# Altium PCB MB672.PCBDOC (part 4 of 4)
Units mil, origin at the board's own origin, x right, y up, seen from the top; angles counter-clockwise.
Board outline 4505 x 6805 mil, 4 copper layers (TopLayer, GND, VCC, BottomLayer); 337 components, 289 nets, 1516 pads, 621 vias.
Unrouted connection lines stored in the file: 46.
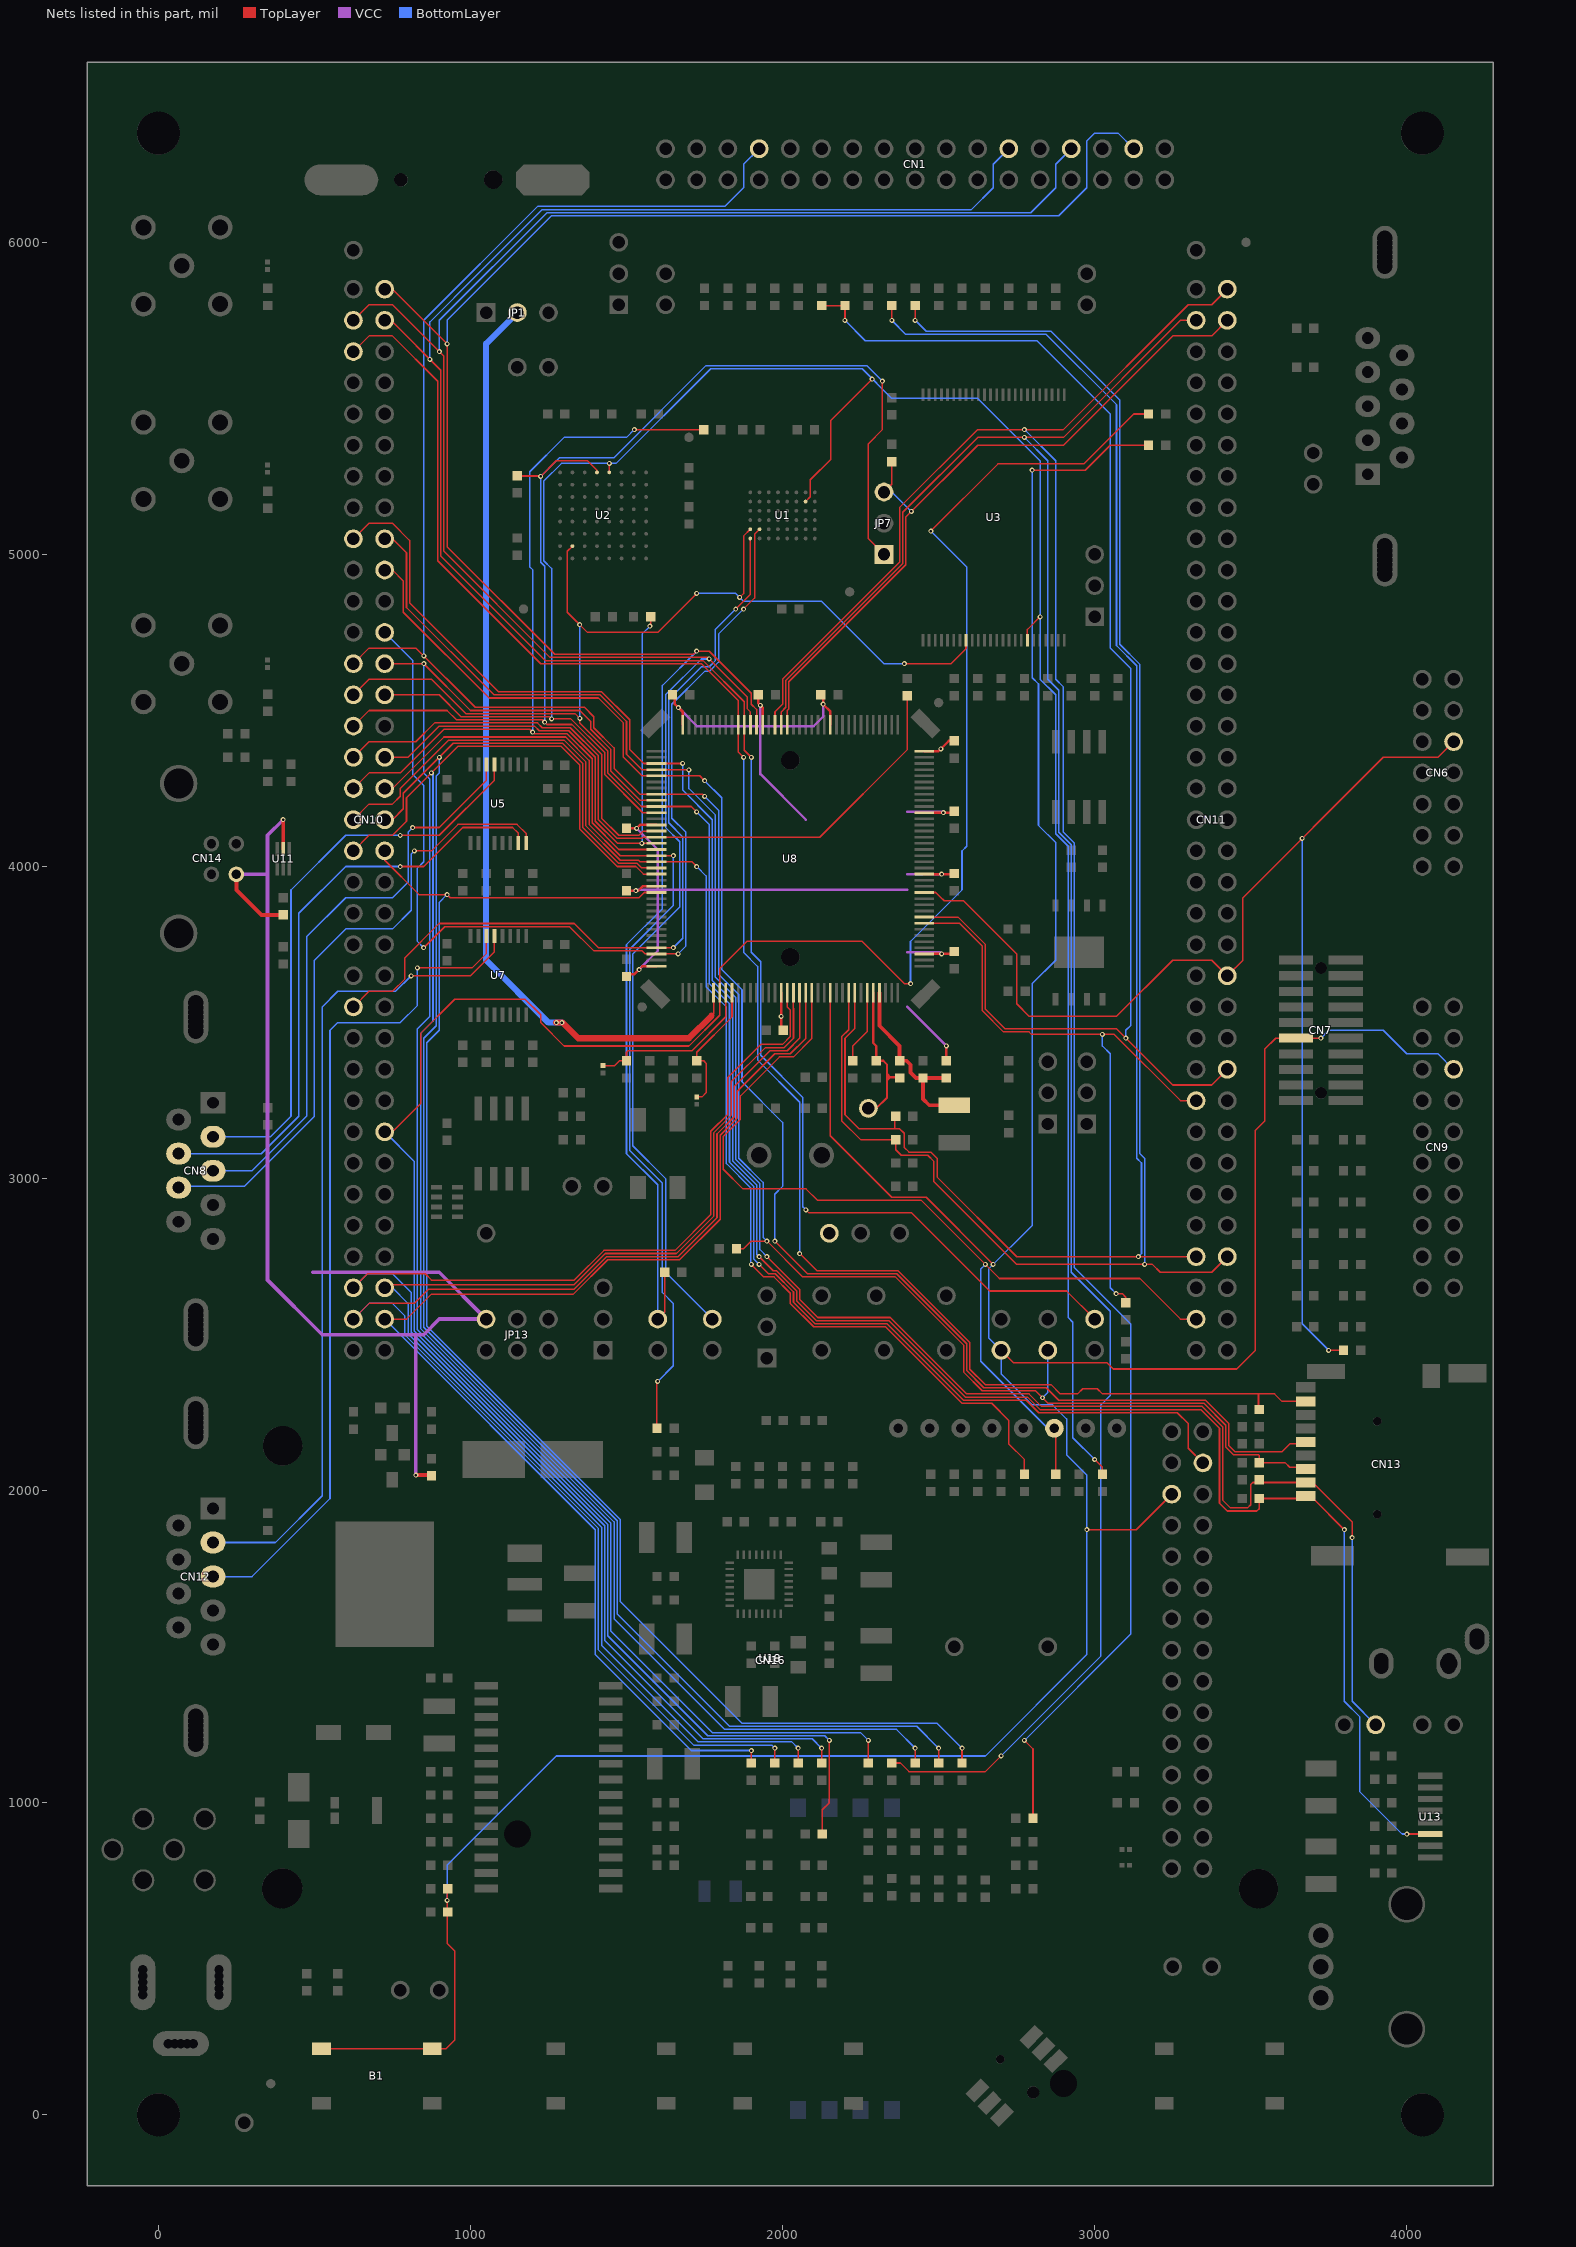
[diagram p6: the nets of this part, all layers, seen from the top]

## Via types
v1: diameter 16, hole 8, TopLayer to BottomLayer, tented both sides, 621 vias

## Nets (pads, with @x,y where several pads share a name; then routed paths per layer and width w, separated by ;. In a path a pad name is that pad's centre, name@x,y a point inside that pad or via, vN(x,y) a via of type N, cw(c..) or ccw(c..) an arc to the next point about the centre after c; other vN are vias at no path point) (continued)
PC2: C13.2 CN11.64 R4.1 U8.28 | length 5545
  TopLayer w5: U8.28@2212.01,3595.87 2212.01,3477.01 2190,3455 2190,3185 2250,3125 C13.2@2362.5,3125 2362.5,3092.5 2380,3075 2465,3075 2485,3055 2485,2990 2750,2725 3185,2725 3210,2700 3375,2700 CN11.64@3425,2750 ; v1(2425,5750) R4.1@2425,5797.5
  BottomLayer w5: v1(2425,5750) 2460,5715 2860,5715 3080,5495 3080,4712.43 3145,4647.43 3145,3080 3160,3065 v1(3160,2725)
PC3: C9.2 CN11.63 R3.1 U8.29 | length 5463.1
  TopLayer w5: U8.29@2231.69,3595.87 2231.69,3481.69 2200,3450 2200,3205 2245,3160 2375,3160 2390,3145 2390,3100 2405,3085 2475,3085 2495,3065 2495,3005 2750,2750 CN11.63@3325,2750 ; v1(2350,5750) R3.1@2350,5797.5 ; 2360,3160 C9.2@2360,3197.5
  BottomLayer w5: v1(2350,5750) 2395,5705 2845,5705 3070,5480 3070,4708.28 3135,4643.28 3135,3065 3150,3050 3150,2760 v1(3140,2750)
PC4: CN11.53 R126.1 U8.44 | length 2132.1
  TopLayer w5: U8.44@2454.13,3818.31 2566.69,3818.31 2640,3745 2640,3538.28 2708.28,3470 2790,3470 2798,3462 3063,3462 3275,3250 CN11.53@3325,3250 ; v1(3068.5,2631.5) 3088.5,2631.5 3100,2620 R126.1@3100,2602.5 R126.1@3097.5,2602.5
  BottomLayer w5: v1(3025,3462) 3025,3425 3050,3400 3050,2650 v1(3068.5,2631.5)
PC5: C6.2 CN11.52 R1.2 U8.45 | length 4465.9
  TopLayer w5: R1.2@2125,5797.5 C6.2@2200,5797.5 v1(2200,5750) ; U8.45@2454.13,3837.99 2562.01,3837.99 2650,3750 2650,3542.43 2712.43,3480 3070,3480 3250,3300 3375,3300 CN11.52@3425,3350
  BottomLayer w5: v1(2200,5750) 2265,5685 2815,5685 3050,5450 3050,4700 3115,4635 3115,3490 3100,3475 v1(3100,3450)
PC6: CN1.3 CN10.2 JP15.1 R56.2 U8.96 | length 7269.3
  TopLayer w5: CN10.2@725,5850 750,5850 v1(925,5675) 925,5025 1270,4680 1715,4680 v1(1725,4690) 1765,4690 1900,4555 1900,4520 1916.73,4503.27 U8.96@1916.73,4454.13 ; JP15.1@1600,2550 1622.5,2572.5 R56.2@1622.5,2700
  BottomLayer w5: v1(925,5675) 925,5750 1260,6085 2885,6085 2975,6175 2975,6325 3000,6350 3075,6350 CN1.3@3125,6300 ; JP15.1@1600,2555 1600,2980 1500,3080 1500,3750 1615,3865 1615,4580 v1(1725,4690)
PC7: CN1.7 CN10.3 JP16.1 U8.97 | length 7033.7
  TopLayer w5: CN10.3@625,5750 675,5800 750,5800 915,5635 915,5010 1255,4670 1760,4670 1887.36,4542.64 1887.36,4505 1897.05,4495.32 U8.97@1897.05,4454.13
  BottomLayer w5: v1(900,5650) 900,5750 1245,6095 2795,6095 2875,6175 2875,6250 CN1.7@2925,6300 ; v1(1765,4665) 1740,4665 1625,4550 1625,4125 1670.44,4079.56 1670.44,3870.44 1520,3720 1520,3105 1625,3000 1625,2700 JP16.1@1775,2550
PC8: CN1.11 CN10.4 JP17.1 U8.98 | length 7035.5
  TopLayer w5: CN10.4@725,5750 745,5750 905,5590 905,4995 1240,4660 1745,4660 1877.36,4527.64 1877.36,4372.64 v1(1900,4350) ; v1(2075,2900) 2085,2890 2414.14,2890 2664.14,2640 2910,2640 JP17.1@3000,2550
  BottomLayer w5: v1(870,5625) 870,5745 1025,5900 1056.28,5931.28 1230,6105 2605,6105 2675,6175 2675,6250 CN1.11@2725,6300 ; v1(1900,4350) 1900,3725 1930,3695 1930,3395 2065,3260 2065,2910 v1(2075,2900)
PC9: CN10.5 CN13.8 R131.2 U8.99 | length 5857.6
  TopLayer w5: CN10.5@625,5650 675,5700 750,5700 895,5555 895,4980 1225,4650 1740,4650 1857.68,4532.32 1857.68,4367.32 v1(1875,4350) ; v1(2055,2760) 2110,2705 2370,2705 2600,2475 2600,2389.14 2649.14,2340 2860,2340 2890,2310 2945,2310 2961.84,2326.84 3008.16,2326.84 3025,2310 3576.22,2310 3600,2286.22 CN13.8@3676.65,2286.22 ; R131.2@3525,2262.5 3525,2310
  BottomLayer w5: v1(1875,4350) 1875,3725 1920,3680 1920,3380 2055,3245 v1(2055,2760)
PC10: CN10.17 CN13.1 R132.2 U8.111 U13.3 | length 6840
  TopLayer w5: CN10.17@625,5050 675,5100 750,5100 805,5045 805,4845 1090,4560 1420,4560 1510,4470 1510,4375.12 1555,4330.12 v1(1680.12,4330.12) ; v1(1925,2750) 1970,2705 1980.86,2705 2045,2640.86 2045,2608.28 2108.28,2545 2340,2545 2585,2300 2785,2300 2825,2260 3340,2260 3400,2200 3400,1960 3425,1935 3520,1935 3527.5,1942.5 R132.2@3527.5,1975 3700,1975 v1(3800,1875) ; v1(4000,900) 4074.8,900 U13.3@4075,899.8
  BottomLayer w5: v1(1680.12,4330.12) 1680.12,4244.88 1775,4150 1775,3635 1840,3570 1840,3056.72 1917.5,2979.22 1917.5,2757.5 v1(1925,2750) ; v1(3800,1875) 3800,1325 3850,1275 3850,1035 3985,900 v1(4000,900)
PC11: CN10.18 CN13.2 JP22.1 R133.2 U8.112 | length 6279.5
  TopLayer w5: CN10.18@725,5050 750,5050 795,5005 795,4830 1075,4550 1415,4550 1500,4465 1500,4360 1549.57,4310.43 1699.57,4310.43 v1(1700,4310) ; v1(1950,2750) 2055,2645 2055,2612.43 2112.43,2555 2345,2555 2590,2310 2790,2310 2830,2270 3345,2270 3410,2205 3410,1970 3435,1945 3490,1945 3500,1955 3500,2020 3506.38,2026.38 3698.62,2026.38 3825,1900 v1(3825,1850)
  BottomLayer w5: v1(1700,4310) 1700,4250 1785,4165 1785,3645 1850,3580 1850,3060.86 1927.5,2983.36 1927.5,2772.5 v1(1950,2750) ; v1(3825,1850) 3825,1325 JP22.1@3900,1250
PC12: CN10.20 CN13.5 U8.113 | length 5102.8
  TopLayer w5: CN10.20@725,4950 750,4950 785,4915 785,4815 1060,4540 1410,4540 1490,4460 1490,4350 1549.25,4290.75 1734.25,4290.75 v1(1750,4275) ; v1(1975,2800) 2080,2695 2365.86,2695 2590,2470.86 2590,2385 2645,2330 2845,2330 2885,2290 3355,2290 3430,2215 3430,2145 3450,2125 3600,2125 3625,2150 CN13.5@3680,2150
  BottomLayer w5: v1(1750,4275) 1805,4220 1805,3670 1870,3605 1870,3310 2000,3180 2000,2975 1975,2950 v1(1975,2800)
PC13: CN10.56 R11.1 R111.2 U8.7 | length 7846.4
  TopLayer w5: CN10.56@725,3150 750,3150 840,3240 840,3465 950,3575 1175,3575 1225,3525 1225,3500 1300,3425 1700,3425 1798.62,3523.62 1798.62,3673.62 1885,3760 2255,3760 2390,3625 v1(2410,3625) ; R111.2@2127.5,900 2127.5,977.5 2150,1000 v1(2150,1200) ; v1(2475,5075) 2690,5290 2965,5290 3125,5450 R11.1@3172.5,5450
  BottomLayer w5: CN10.56@725,3150 820,3055 820,2511.57 1440,1891.57 1440,1535 1760,1215 2135,1215 v1(2150,1200) ; v1(2410,3625) 2410,3760 2575,3925 2575,4050 2590,4065 2590,4960 v1(2475,5075)
PC14: JP9.1 R135.2 U8.8 | length 551.8
  TopLayer w5: JP9.1@1425,3361.81 1461.81,3361.81 1477.5,3377.5 R135.2@1500,3377.5 1500,3405 1505,3410 1710,3410 1818.31,3518.31 U8.8@1818.31,3595.87
PC15: JP10.2 R39.2 U8.9 | length 428.7
  TopLayer w5: JP10.2@1725,3261.81 1741.81,3261.81 1755,3275 1755,3370 1747.5,3377.5 R39.2@1725,3377.5 1725,3405 1837.99,3517.99 U8.9@1837.99,3595.87
PD2: C60.2 CN1.27 CN10.25 CN13.3 JP20.1 R134.2 U8.116 | length 7723.2
  TopLayer w5: CN10.25@625,4650 675,4700 825,4700 1015,4510 1365,4510 1395,4480 1395,4445 1460,4380 1460,4315 1543.31,4231.69 1743.31,4231.69 v1(1750,4225) ; C60.2@1852.5,2775 1875,2775 1900,2800 v1(1950,2800) 2065,2685 2361.72,2685 2580,2466.72 2580,2380 2640,2320 2810.74,2320 2850.74,2280 3350,2280 3420,2210 3420,2140 3445,2115 3525,2115 3527.5,2112.5 R134.2@3527.5,2090 3610,2090 3625,2075 CN13.3@3670,2075
  BottomLayer w5: v1(850.35,4674.65) 850.35,5750.35 1215,6115 1815,6115 1875,6175 1875,6250 CN1.27@1925,6300 ; v1(1750,4225) 1795,4180 1795,3655 1860,3590 1860,3065 1937.5,2987.5 1937.5,2812.5 v1(1950,2800) ; v1(2832.87,2297.87) 2850,2315 JP20.1@2850,2450
PD3: CN10.26 R100.2 U8.117 | length 5532.8
  TopLayer w5: CN10.26@725,4650 v1@850,4650 ; v1(850.35,4650.35) v1@850,4650 ; U8.117@1595.87,4212.01 1542.99,4212.01 1450,4305 1450,4375 1385,4440 1385,4465 1350,4500 1000,4500 v1@850,4650 ; R100.2@2275,1127.5 v1(2275,1200)
  BottomLayer w5: v1(850.35,4650.35) 850.35,4299.65 870,4280 870,3520 830,3480 830,2515.71 1450,1895.71 1450,1550 1775,1225 2250,1225 v1(2275,1200)
PD4: CN10.27 CN16.4 U1.A2 U2.G2 U3.8 U8.118 | length 6877.7
  TopLayer w5: CN10.27@625,4550 675,4600 875,4600 985,4490 1335,4490 v1(1350.36,4474.64) 1350.36,4459.64 1440,4370 1440,4300 1547.68,4192.32 1707.68,4192.32 v1(1725,4175) ; U2.G2@1326.57,5026.57 1310,5010 1310,4815 1375,4750 1600,4750 v1(1725,4875) ; v1(1862.61,4862.39) 1875,4874.78 1875,5059.06 U1.A2@1896.65,5080.71 ; v1(1925,2725) 1955,2695 1976.72,2695 2035,2636.72 2035,2604.14 2104.14,2535 2335,2535 2580,2290 2780.86,2290 2820.86,2250 3265,2250 3300,2215 3300,2136 CN16.4@3347,2089 ; v1(2390,4650) 2540,4650 2587.8,4697.8 U3.8@2587.8,4725
  BottomLayer w5: v1@1350,4475 v1(1350,4775) ; v1(1725,4175) 1765,4135 1765,3625 1830,3560 1830,3052.57 1907.5,2975.07 1907.5,2742.5 v1(1925,2725) ; v1(1725,4875) 1850,4875 1875,4850 2125,4850 2325,4650 v1(2390,4650)
PD5: CN10.28 R80.1 U1.G5 U2.A5 U3.18 U8.119 | length 7633.3
  TopLayer w5: CN10.28@725,4550 900,4550 970,4480 1253,4480 v1(1260,4473) 1322,4473 1430,4365 1430,4295 1552.36,4172.64 U8.119@1595.87,4172.64 ; U2.A5@1444.68,5262.8 v1@1444.68,5291.21 ; U1.G5@2073.82,5169.29 2089,5184.47 2089,5239 2155,5305 2155,5430 v1(2286.99,5561.99) ; U3.18@2784.65,4725 2784.65,4759.65 v1(2825,4800) ; v1(3000,2100) 3025,2075 R80.1@3025,2052.5
  BottomLayer w5: v1(1260,4473) 1260,4955 1235,4980 1235,5235 1291.52,5291.52 1466.52,5291.52 1770,5595 2255,5595 2350,5500 2625,5500 2825,5300 2825,4600 2875,4550 2875,4105 2915,4065 2915,2555 2930,2540 2930,2170 v1(3000,2100)
  other v1: 1445,5291.52
PD6: CN10.29 JP7.1 R18.1 U2.A4 U8.122 | length 4225.9
  TopLayer w5: CN10.29@625,4450 675,4500 925,4500 955,4470 1230,4470 1245,4455 1325,4455 1420,4360 1420,4155 1475,4100 1540,4100 1553.58,4113.58 U8.122@1595.87,4113.58 ; R18.1@1151.14,5251.36 v1@1223.64,5251.36 ; v1(1225,5250) 1275,5300 1375,5300 1405.31,5269.69 U2.A4@1405.31,5262.8 ; v1(2320,5555) 2320,5400 2275,5355 2275,5050 JP7.1@2325,5000
  BottomLayer w5: v1(1237.61,4462.39) 1237.61,4962.39 1225,4975 v1(1225,5250) 1285,5310 1460,5310 1755,5605 2270,5605 v1(2320,5555)
PD7: CN10.31 R22.1 U8.123 | length 2384.5
  TopLayer w5: CN10.31@625,4350 675,4400 825,4400 885,4460 1215,4460 1230,4445 1320,4445 1410,4355 1410,4150 1470,4090 1550,4090 1553.9,4093.9 2118.9,4093.9 2400,4375 R22.1@2400,4547.5
PE0: CN10.47 U1.A1 U8.141 | length 2673.6
  TopLayer w5: CN10.47@625,3550 675,3600 750,3600 790,3640 790,3708 899.36,3817.36 1332.64,3817.36 1410.43,3739.57 U8.141@1595.87,3739.57 1596.3,3740 v1(1650,3740) ; v1(1850,4825) 1896.65,4871.65 U1.A1@1896.65,5051.18
  BottomLayer w5: v1(1650,3740) 1680.44,3770.44 1680.44,4094.56 1635,4140 1635,4535 1740,4640 1765,4640 1785,4660 1785,4760 v1(1850,4825)
PE1: CN10.24 U1.B2 U8.142 | length 3472.9
  TopLayer w5: v1(850,3740) 917.36,3807.36 1317.64,3807.36 1395.43,3729.57 1550.43,3729.57 1560.12,3719.88 v1(1665,3719.88) ; v1(1875,4825) 1910.47,4860.47 1910.47,5065 U1.B2@1926.18,5080.71
  BottomLayer w5: CN10.24@725,4750 815,4660 815,4295 850,4260 850,4015 830,3995 830,3760 v1(850,3740) ; v1(1665,3719.88) 1690.44,3745.33 1690.44,4109.56 1645,4155 1645,4520 1750,4625 1765,4625 1795,4655 1795,4745 v1(1875,4825)
PF6: CN10.65 R96.2 U8.18 | length 4606.2
  TopLayer w5: CN10.65@625,2650 670,2695 855,2695 875,2675 1332.57,2675 1427.57,2770 1655,2770 1770,2885 1770,3151.57 1825,3206.57 1825,3325 1930,3430 2000,3430 2025,3455 2025,3540 2015.16,3549.84 U8.18@2015.16,3595.87 ; R96.2@2125,1127.5 v1(2125,1175)
  BottomLayer w5: CN10.65@625,2650 670,2695 750,2695 810,2635 810,2507.43 1430,1887.43 1430,1520 1745,1205 2095,1205 v1(2125,1175)
PF7: CN10.66 R97.2 U8.19 | length 4268.7
  TopLayer w5: CN10.66@725,2650 735,2660 1331.72,2660 1431.72,2760 1660,2760 1780,2880 1780,3147.43 1835,3202.43 1835,3310 1945,3420 2005,3420 2035,3450 2035,3545 2034.84,3545.16 U8.19@2034.84,3595.87 ; R97.2@2050,1127.5 v1(2050,1175)
  BottomLayer w5: CN10.66@725,2650 750,2650 800,2600 800,2503.28 1420,1883.28 1420,1505 1730,1195 2030,1195 v1(2050,1175)
PF8: CN10.67 R98.2 U8.20 | length 4434.3
  TopLayer w5: CN10.67@625,2550 675,2600 820,2600 865,2645 1330.86,2645 1435.86,2750 1665,2750 1790,2875 1790,3143.28 1845,3198.28 1845,3295 1960,3410 2015,3410 2054.53,3449.53 U8.20@2054.53,3595.87 ; R98.2@1975,1127.5 v1(1975,1175)
  BottomLayer w5: CN10.67@625,2550 675,2600 750,2600 790,2560 790,2499.14 1410,1879.14 1410,1490 1715,1185 1965,1185 v1(1975,1175)
PF9: CN10.68 R99.2 U8.21 | length 4098.3
  TopLayer w5: CN10.68@725,2550 795,2550 875,2630 1330,2630 1440,2740 1670,2740 1800,2870 1800,3139.14 1855,3194.14 1855,3280 1975,3400 2025,3400 2074.21,3449.21 U8.21@2074.21,3595.87 ; R99.2@1900,1127.5 v1(1900,1167.52)
  BottomLayer w5: CN10.68@725,2550 1400,1875 1400,1475 1707.48,1167.52 v1(1900,1167.52)
PF10: CN11.67 R78.1 U8.22 U18.6 | length 3208.5
  TopLayer w5: U8.22@2093.9,3595.87 2093.9,3448.9 2035,3390 1990,3390 1865,3265 1865,3190 1810,3135 1810,3030 1872.93,2967.07 2075.36,2967.07 2112.43,2930 2445,2930 2695,2680 3145,2680 3275,2550 CN11.67@3325,2550 ; R78.1@2875,2052.5 U18.6@2875,2196.06
  BottomLayer w5: v1(2650,2725) 2635,2710 2635,2415 2850,2200 U18.6@2871.06,2200
PF11: CN6.9 CN11.46 R129.1 U8.49 | length 4198.7
  TopLayer w5: U8.49@2454.13,3916.73 2490.94,3916.73 2502.65,3905.03 ; 2503.36,3904.32 2517.68,3890 2580,3890 2750,3720 2750,3560 2790,3520 3070,3520 3250,3700 3375,3700 CN11.46@3425,3650 3475,3700 3475,3900 3925,4350 4100,4350 CN6.9@4150,4400 ; v1(3750,2450) R129.1@3797.5,2450
  BottomLayer w5: v1(3665,4090) 3665,2535 v1(3750,2450)
PG6: CN11.4 JP7.3 R17.1 U8.91 | length 2335.5
  TopLayer w5: U8.91@2015.16,4454.13 2015.16,4500.16 2020,4505 2020,4591.72 2395,4966.72 2395,5120 2625,5350 2900,5350 3250,5700 3375,5700 CN11.4@3425,5750 ; JP7.3@2325,5200 2350,5225 R17.1@2350,5297.5
  BottomLayer w5: JP7.3@2325,5200 2350,5200 2412.38,5137.62 v1(2412.62,5137.62)
PG7: CN11.3 R101.2 U8.92 | length 6902.9
  TopLayer w5: U8.92@1995.47,4454.13 1995.47,4495.47 2010,4510 2010,4595.86 2385,4970.86 2385,5135 2625,5375 2900,5375 3275,5750 CN11.3@3325,5750 ; R101.2@2350,1127.5 2377.5,1127.5 2405,1100 2650,1100 v1(2700,1150)
  BottomLayer w5: v1(2700,1150) 3020,1470 3020,2275 3050,2305 3050,2575 2925,2700 2925,4070 2885,4110 2885,4565 2850,4600 2850,5300 v1(2775,5375)
PG8: CN11.2 R106.2 U8.93 | length 6944.2
  TopLayer w5: U8.93@1975.79,4454.13 1975.79,4495.79 2000,4520 2000,4600 2375,4975 2375,5150 2625,5400 2900,5400 3300,5800 3375,5800 CN11.2@3425,5850 ; v1(2775,1200) 2802.5,1172.5 R106.2@2802.5,950
  BottomLayer w5: v1(2775,1200) 3115,1540 3115,2535 2935,2715 2935,4075 2900,4110 2900,4575 2875,4600 2875,5300 v1(2775,5400)
PG9: CN10.32 R21.1 U8.124 | length 1923.5
  TopLayer w5: CN10.32@725,4350 800,4350 900,4450 1205,4450 1220,4435 1315,4435 1400,4350 1400,4145 1470.79,4074.21 v1@1548,4074.21 ; v1@1548.88,4074.21 U8.124@1595.87,4074.21 ; v1(1575,4770) 1577.5,4772.5 R21.1@1577.5,4800
  BottomLayer w5: v1@1550,4075 1550,4745 v1(1575,4770)
  other v1: 1548.88,4073.88
PG10: CN10.33 R15.1 U8.125 | length 2781.3
  TopLayer w5: CN10.33@625,4250 675,4300 775,4300 915,4440 1190,4440 1205,4425 1310,4425 1390,4345 1390,4140 1475.47,4054.53 U8.125@1595.87,4054.53 ; v1(1525,5400) R15.1@1747.5,5400
  BottomLayer w5: v1(1199.04,4430.96) 1200,4431.92 1200,4950 1190,4960 1190,5265 1300,5375 1500,5375 v1(1525,5400)
PG11: CN10.34 R128.2 U8.126 | length 3243.7
  TopLayer w5: CN10.34@725,4250 750,4250 915,4415 1305,4415 1380,4340 1380,4135 1480.16,4034.84 U8.126@1595.87,4034.84 1596.02,4035 v1(1650,4035) ; R128.2@1597.5,2200 1597.5,2347.5 v1(1600,2350)
  BottomLayer w5: v1(1600,2350) 1650,2400 1650,2600 1615,2635 1615,2985 1510,3090 1510,3735 1650,3875 v1(1650,4035)
PG12: CN10.35 R77.1 U8.127 | length 4100
  TopLayer w5: CN10.35@625,4150 675,4200 750,4200 775,4225 775,4250 930,4405 1300,4405 1370,4335 1370,4130 1480,4020 1538.28,4020 1543.13,4015.16 1709.84,4015.16 v1(1725,4000) ; v1(1900,2725) 1940,2685 1972.57,2685 2025,2632.57 2025,2600 2100,2525 2330,2525 2575,2280 2670,2280 2725,2225 2725,2150 2775,2100 R77.1@2775,2052.5
  BottomLayer w5: v1(1725,4000) 1755,3970 1755,3615 1820,3550 1820,3048.43 1897.5,2970.93 1897.5,2727.5 v1(1900,2725)
PG13: CN10.36 R103.2 U8.128 | length 5565.3
  TopLayer w5: CN10.36@725,4150 750,4150 785,4185 785,4235 945,4395 1295,4395 1360,4330 1360,4125 1475,4010 1534.14,4010 1548.67,3995.47 U8.128@1595.87,3995.47 ; R103.2@2500,1127.5 v1(2500,1175)
  BottomLayer w5: v1(900,4350) 900,4300 890,4290 890,3490 850,3450 850,2524 1470,1904 1470,1605 1830,1245 2430,1245 v1(2500,1175)
PG14: CN10.37 R102.2 U8.129 | length 5613
  TopLayer w5: CN10.37@625,4050 675,4100 750,4100 795,4145 795,4220 960,4385 1290,4385 1350,4325 1350,4120 1470,4000 1530,4000 1554.21,3975.79 U8.129@1595.87,3975.79 ; R102.2@2425,1127.5 v1(2425,1175)
  BottomLayer w5: v1(875,4300) 880,4295 880,3505 840,3465 840,2519.85 1460,1899.85 1460,1590 1815,1235 2365,1235 v1(2425,1175)
PG15: CN10.38 R104.2 U8.132 | length 4843.4
  TopLayer w5: CN10.38@725,4050 725,4020 835,3910 v1(925,3910) 935,3900 1540,3900 1556.73,3916.73 U8.132@1595.87,3916.73 ; R104.2@2575,1127.5 v1(2575,1175)
  BottomLayer w5: v1(925,3910) 900,3885 900,3475 860,3435 860,2528.14 1480,1908.14 1480,1645 1870,1255 2495,1255 v1(2575,1175)
RESET#: B1.2 B1.3 C94.2 CN7.10 CN9.15 CN16.5 JP19.2 R14.2 R119.1 U8.25 | length 11857.3
  TopLayer w5: B1.2@522.83,212.5 922.5,212.5 950,240 950,525 925,550 R119.1@925,722.5 ; U8.25@2152.95,3595.87 2152.95,3137.05 2350,2940 2460,2940 v1(2675,2725) ; JP19.2@2700,2450 2740,2410 3039.85,2410 3059.85,2390 3455,2390 3515,2450 3515,3155 3545,3185 3545,3415 3580,3450 v1(3725,3450) ; v1(2800,5270) 2970,5270 3050,5350 R14.2@3172.5,5350 ; v1(2975,1875) 3133,1875 CN16.5@3247,1989
  BottomLayer w5: v1(925,687.5) 925,800 1275,1150 2650,1150 2975,1475 2975,2050 2910,2115 2910,2230 2865,2275 2800,2275 2700,2375 JP19.2@2700,2450 2660,2490 2660,2710 2800,2850 2800,3625 2875,3700 2875,4076.72 2820,4131.72 2820,4585 2800,4605 v1(2800,5270) ; v1(3725,3450) 3750,3475 3925,3475 4000,3400 4100,3400 CN9.15@4150,3350
RS232_CTS2: CN8.8 U5.8 | length 2031.4
  TopLayer w5: v1(820,4050) 875,4050 960,4135 1149.13,4135 1179.13,4105 U5.8@1179.13,4075
  BottomLayer w5: CN8.8@69,2975 275,2975 500,3200 500,3700 600,3800 750,3800 810,3860 810,4040 v1(820,4050)
RS232_RTS2: CN8.7 U5.7 | length 1941.3
  TopLayer w5: v1(775,4000) 850,4000 975,4125 1135,4125 1153.54,4106.46 U5.7@1153.54,4075
  BottomLayer w5: CN8.7@65,3080 330,3080 450,3200 450,3850 600,4000 v1(775,4000)
RS232_RX1: CN12.2 U7.13 | length 2653.3
  TopLayer w5: v1(810,3650) 1000,3650 1076.77,3726.77 U7.13@1076.77,3776.97
  BottomLayer w5: CN12.2@175,1834 375,1834 525,1984 525,3550 575,3600 760,3600 v1(810,3650)
RS232_RX2: CN8.2 U5.13 | length 1850
  TopLayer w5: v1(775,4100) 900,4100 1076.77,4276.77 U5.13@1076.77,4326.97
  BottomLayer w5: CN8.2@175,3134 359,3134 425,3200 425,3925 600,4100 v1(775,4100)
RS232_TX1: CN12.3 U7.14 | length 2707.8
  TopLayer w5: v1(830,3675) 1005,3675 1051.18,3721.18 U7.14@1051.18,3776.97
  BottomLayer w5: CN12.3@175,1725 300,1725 550,1975 550,3475 575,3500 775,3500 830,3555 v1(830,3675)
RS232_TX2: CN8.3 U5.14 | length 1875.8
  TopLayer w5: v1(815,4125) 900,4125 1051.18,4276.18 U5.14@1051.18,4326.97
  BottomLayer w5: CN8.3@175,3025 300,3025 475,3200 475,3775 600,3900 750,3900 800,3950 800,4110 v1(815,4125)
U5V: C74.2 CN14.1 JP13.2 R70.1 U11.5 | length 3830.4
  TopLayer w12: CN14.1@250,3975 250,3925 330,3845 C74.2@400,3845 ; U11.5@400,4056.3 v1(400,4150) ; v1(825,2050) R70.1@872.5,2050
  VCC w12: CN14.1@250,3975 350,3975 ; v1(400,4150) 350,4100 350,2675 525,2500 850,2500 900,2550 JP13.2@1050,2550 900,2700 495,2700 ; v1(825,2050) 825,2500
VBAT: JP1.2 U8.6 | length 3066
  TopLayer w5: 1772.54,3522.54 1778.94,3528.94 U8.6@1778.94,3595.87
  TopLayer w20: v1(1275,3500) 1295,3500 1345,3450 1700,3450 1772.54,3522.54
  BottomLayer w20: JP1.2@1150,5775 1050,5675 1050,3700 1250,3500 v1(1292.5,3500)
VDD: C17.1 C18.1 C19.1 C23.1 C25.1 C26.1 C32.1 C33.1 C35.1 C36.1 C38.1 JP12.1 L1.2 U8.17 U8.39 U8.52 U8.62 U8.72 U8.84 U8.95 U8.108 U8.121 U8.131 U8.144 | length 4043.7
  TopLayer w8: C35.1@1495,3655 1525,3655 1550.51,3680.51 U8.144@1595.87,3680.51 ; C32.1@1500,3922.5 1537.5,3922.5 1551.42,3936.42 U8.131@1595.87,3936.42 ; C25.1@1500,4122.5 v1(1532.5,4122.5) 1543.27,4133.27 U8.121@1595.87,4133.27 ; C17.1@1655,4550 1655,4520 1680.51,4494.49 U8.108@1680.51,4454.13 ; C18.1@1922.5,4550 1922.5,4522.5 1936.42,4508.58 U8.95@1936.42,4454.13 ; C38.1@1995.47,3470.47 U8.17@1995.47,3595.87 ; C19.1@2130,4550 v1(2130,4520) 2152.95,4497.05 U8.84@2152.95,4454.13 ; U8.39@2454.13,3719.88 C36.1@2542.38,3719.88 ; U8.52@2454.13,3975.79 C33.1@2548.29,3975.79 ; U8.62@2454.13,4172.64 C26.1@2547.36,4172.64 ; U8.72@2454.13,4369.49 2499.49,4369.49 2532.5,4402.5 C23.1@2550,4402.5 ; L1.2@2525,3377.5 v1(2525,3425)
  VCC w8: v1(1530,3922.5) 1532.5,3925 2400,3925 ; v1(1532.5,4122.5) 1600,4055 1600,3730 v1(1540,3670) ; v1(1666.09,4508.91) 1725,4450 2100,4450 2130,4480 v1(2130,4520) ; v1(1928.95,4516.05) 1928.95,4296.05 2075,4150 ; 2400,3550 v1(2525,3425) ; 2400,3725 2504.88,3725 v1(2510,3719.88) ; 2400,3975 2509.21,3975 v1(2510,3975.79) ; 2400,4175 2512.64,4175 v1(2515,4172.64)
  other v1: 1995.47,3519.53 2506.86,4376.86
VDDA: C46.2 C50.1 L1.1 R42.2 U8.33 | length 608.3
  TopLayer w12: U8.33@2310.43,3595.87 2310.43,3489.57 2375,3425 R42.2@2375,3377.5 2397.5,3377.5 2410,3365 2410,3340 2427.5,3322.5 L1.1@2525,3322.5 ; C46.2@2450,3322.5 2450,3255 2470,3235 C50.1@2550,3235
VREF+: C45.1 R42.1 TP3.1 U8.32 | length 520.2
  TopLayer w7: TP3.1@2275,3225 2300,3225 2335,3260 2335,3365 2322.5,3377.5 C45.1@2300,3377.5 2300,3425 2290.75,3434.25 U8.32@2290.75,3595.87 ; 2335,3315 2345,3325 2335,3335 ; 2335,3325 R42.1@2385,3325
VREF-: R41.1 U8.31 | length 237.4
  TopLayer w5: R41.1@2225,3377.5 2225,3425 2271.06,3471.06 U8.31@2271.06,3595.87
pads on no net: BT1.0 CN4.1 CN4.4 CN4.8 CN6.12 CN7.0 CN7.7 CN8.9 CN10.11 CN11.38 CN11.48 CN11.49 CN11.62 CN11.68 CN12.9 CN13.0 CN16.0 CN18.6 CN18.G0 R51.2 U1.A6 U1.E3 U1.G2 U1.H6 U2.A1 U2.A8 U2.B1 U2.C1 U2.C8 U2.D1 U2.E1 U2.F8 U2.G1 U2.G8 U2.H1 U2.H8 U4.5 U6.0 U7.7 U7.8 U7.9 U8.0 U8.106 U10.0 U10.1 U10.5 U10.12 U10.26 U10.27 U10.28 U10.29 U10.30 U13.2 U17.10 U17.25 U18.0 U19.0 X2.2 X2.3
copper on no net: | length 12020
  TopLayer w5: -225,2200 -100,2200 ; -225,2325 -100,2325 25,2325 ; -225,2450 -100,2450 25,2450 ; -120,2200 25,2200 ; -100,1950 -100,2075 ; -100,2700 -100,2575 ; -225,2075 -225,1950 25,1950 25,2075 ; -225,2075 -100,2075 ; -225,2075 -225,2575 ; -225,2575 -225,2700 20,2700 25,2700 25,2575 ; -225,2575 -100,2575 ; -100,2075 -100,2575 ; -100,2075 25,2075 ; -100,2575 25,2575 ; 25,2075 25,2575
  VCC w5: -225,2075 25,2075 ; -225,2200 25,2200 ; -225,2325 25,2325 ; -225,2450 25,2450 ; -100,1950 -100,2575 -100,2700 ; -225,2575 -225,2700 25,2700 25,2575 ; -225,2575 -225,1950 25,1950 25,2575 ; -225,2575 25,2575
  BottomLayer w5: -225,2200 -100,2200 25,2200 ; -225,2325 -100,2325 25,2325 ; -225,2450 -100,2450 25,2450 ; -100,1950 -100,2075 ; -100,2700 -100,2575 ; -225,2075 -225,1950 25,1950 25,2075 ; -225,2075 -100,2075 ; -225,2075 -225,2575 ; -225,2575 -225,2700 25,2700 25,2575 ; -225,2575 -100,2575 ; -100,2075 -100,2575 ; -100,2075 25,2075 ; -100,2575 25,2575 ; 25,2075 25,2575

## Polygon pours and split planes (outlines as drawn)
GND on TopLayer "TopLayer-GND" (hatched 90Degree grid 20 track 10, remove dead copper, pour order 0): -210,6560 4290,6560 4290,-240 -210,-240
NetC78_2 on TopLayer "TopLayer-NetC78_2" (hatched 90Degree grid 10 track 15, remove dead copper, pour order 1): -225,4475 250,4475 250,3725 -225,3725
+3V3 on VCC "VCC-+3V3" (hatched 90Degree grid 10 track 15, remove dead copper, pour order 2): -225,6575 4275,6575 4275,-225 -225,-225
+5V on VCC "VCC-+5V" (hatched 90Degree grid 10 track 15, remove dead copper, pour order 3): 1925,6300 1925,6575 4275,6575 4275,-225 -225,-225 -225,895 450,895 635,1080 635,1660 1000,2025 1000,2490.05 1275,2490.05 1275,1925 1125,1775 1025,1775 975,1725 975,1375 1025,1325 1025,1025 775,775 775,400 1225,-50 3475,-50 4075,550 4075,1150 3900,1325 3900,2275 4200,2575 4200,3850 4150,3900 4025,3900 4025,4100 4150,4100 4150,5950 3875,6225 1920,6225 1920,6340
E5V on VCC "VCC-E5V" (hatched 90Degree grid 10 track 15, remove dead copper, pour order 4): -220,775 400,775 650,1025 650,1650 1025,2025 1025,2425 1050,2450 1270,2450 1270,2625 815,2625 815,2000 500,1685 500,1200 375,1075 -225,1075 -225,775
D5V on VCC "VCC-D5V" (hatched 90Degree grid 10 track 15, remove dead copper, pour order 5): 1060,2510 1200,2510 1200,2795 1050,2945 930,2945 900,2975 900,3400 825,3475 700,3475 625,3550 625,5850 775,6000 3000,6000 3125,5875 3125,4875 3400,4875 3400,5900 3105,6195 580,6195 475,6090 475,2795 565,2705 930,2705 1050,2585 1050,2515
U5V on VCC "VCC-U5V" (hatched 90Degree grid 10 track 15, remove dead copper, pour order 6): 225,4200 450,4200 450,2800 500,2750 925,2750 1100,2575 1100,2525 950,2525 880,2455 515,2455 350,2620 250,2720 225,2745
VDD on VCC "VCC-VDD" (hatched 90Degree grid 10 track 10, remove dead copper, pour order 7): 2200,2795 2200,3320 2225,3345 2600,3345 2600,4425 2575,4450 2375,4450 2245,4580 1475,4580 1475,3270 1885,2860 1970,2775 2200,2775
GND on BottomLayer "BottomLayer-GND" (hatched 90Degree grid 20 track 10, remove dead copper, pour order 8): -230,6575 4275,6575 4275,-225 -225,-225 -225,6575
no net on GND (split plane): -102.04,2200 -102.96,2200 -103.12,2200.78 -103.56,2201.44 -104.22,2201.88 -105,2202.04 -207.4,2202.04 -207.4,2322.96 -102.04,2322.96
no net on GND (split plane): 4257.4,-207.4 -207.4,-207.4 -207.4,1930 50,1930 50,2200 50,2325 50,2725 -207.4,2725 -207.4,6557.4 4257.4,6557.4
no net on GND (split plane): 22.96,2202.04 -97.96,2202.04 -97.96,2322.96 22.96,2322.96

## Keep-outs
KeepOutLayer:
  lines w4: -225,1950 -225,2075 ; -225,2200 -100,2200 25,2200 ; -225,2325 -100,2325 25,2325 ; -225,2450 -100,2450 25,2450 ; -100,1950 -100,2075 ; 25,1950 25,2075 ; -225,2075 -100,2075 ; -225,2075 -225,2575 -100,2575 ; -100,2075 25,2075 ; -100,2075 -100,2575 ; -100,2575 25,2575 25,2075
  lines w5: -225,1950 25,1950 ; -225,-225 -225,6575 4275,6575 4275,2361.13 ccw(c5430.29,2115.57) 4275,1870 4275,-225 -225,-225

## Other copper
TopLayer:
  text "1" at -125,2125 h50 r90
  text "D" at -15,2115 h50 r90
VCC:
  text "3" at -125,2410 h50 r90
  text "D" at -15,2410 h50 r90
BottomLayer:
  text "4" at -125,2535 h50 r90
  text "D" at -15,2535 h50 r90
GND (plane layer: these items are gaps in the copper):
  rectangle: -250,2325 50,2725
  region: -225,2200 -225,2325 -250,2325 -250,2200
  region: 50,2200 50,2325 25,2325 25,2200
  region: 50,1930 50,2200 -250,2200 -250,1930
  lines w4: -225,1950 -225,2075 ; -225,2200 -105,2200 ; -225,2325 -100,2325 25,2325 ; -225,2450 -100,2450 25,2450 ; -105,2075 -100,2075 ; -100,1950 -100,2075 ; -100,2200 25,2200 ; 25,1950 25,2075 ; -225,2075 -100,2075 ; -225,2075 -225,2575 -100,2575 ; -100,2075 -100,2575 ; -100,2075 25,2075 ; -100,2575 25,2575 25,2075
  text "2" at -125,2245 h50 r90
  text "D" at -15,2245 h50 r90

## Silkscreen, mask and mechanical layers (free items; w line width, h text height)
TopOverlay:
  drawing of 6002 lines, arcs and shapes, not listed
  text "Motor control" at 2100,6445 h40
  text "1" at 3220,6440 h35
  text "ADC123_11" at 100,6165 h35
  text "GND" at 475,5995 h35
  text "GND" at 3170,5970 h35
  text "CAN" at 3755,5945 h40 r90
  text "1" at 560,5920 h35
  text "2" at 700,5920 h35
  text "1" at 3270,5920 h35
  text "2" at 3400,5920 h35
  text "USART2_CTS" at 1415,5880 h35 r90
  text "GND" at 445,5825 h35
  text "PC6" at 785,5825 h35
  text "GND" at 3150,5825 h35
  text "PG8" at 3485,5825 h35
  text "1" at 1545,5775 h35
  text "1" at 960,5750 h35
  text "MC_EnA" at 1716,5750 h35 r90
  text "MC_Stop" at 3080,5750 h35 r90
  text "PC7" at 445,5725 h35
  text "PC8" at 785,5725 h35
  text "PG7" at 3150,5725 h35
  text "PG6" at 3485,5725 h35
  text "VBAT" at 1025,5680 h35
  text "3V3" at 1175,5680 h35
  text "MC_EnA" at 1410,5675 h35 r90
  text "PC9" at 445,5625 h35
  text "PA8" at 785,5625 h35
  text "PG5" at 3150,5625 h35
  text "PG4" at 3485,5625 h35
  text "ADC123_12" at 100,5545 h35
  text "WP" at 1000,5545 h35
  text "PG3" at 3150,5535 h35
  text "PA9" at 445,5525 h35
  text "PA10" at 785,5525 h35
  text "PG2" at 3485,5525 h35
  text "PC13" at 3150,5480 h35
  text "PA0" at 445,5425 h35
  text "GND" at 790,5425 h35
  text "GND" at 3485,5425 h35
  text "RST" at 3150,5380 h35
  text "PA11" at 790,5325 h35
  text "PD13" at 3485,5325 h35
  text "PA12" at 445,5225 h35
  text "PA13" at 785,5225 h35
  text "PD12" at 3150,5225 h35
  text "PD11" at 3485,5225 h35
  text "PA14" at 445,5125 h35
  text "PA15" at 785,5125 h35
  text "PD10" at 3150,5125 h35
  text "PD9" at 3485,5125 h35
  text "CAN" at 3650,5125 h35
  text "PC10" at 445,5025 h35
  text "PC11" at 785,5025 h35
  text "PD8" at 3150,5025 h35
  text "PB15" at 3485,5025 h35
  text "1" at 2400,4975 h35
  text "NAND_RB" at 2265,4950 h35 r90
  text "GND" at 445,4925 h35
  text "PC12" at 785,4925 h35
  text "D5V" at 3150,4925 h35
  text "PB14" at 3485,4925 h35
  text "ADC123_13" at 100,4890 h35
  text "PD0" at 450,4825 h35
  text "PD1" at 785,4825 h35
  text "PB13" at 3150,4825 h35
  text "PB12" at 3485,4825 h35
  text "CAN speed" at 3100,4750 h35 r90
  text "PE2" at 450,4725 h35
  text "PE1" at 785,4725 h35
  text "PB11" at 3150,4725 h35
  text "PB10" at 3485,4725 h35
  text "1" at 2980,4700 h35
  text "PD2" at 450,4625 h35
  text "PD3" at 785,4625 h35
  text "PE15" at 3150,4625 h35
  text "PE14" at 3485,4625 h35
  text "PD4" at 450,4525 h35
  text "PD5" at 785,4525 h35
  text "PE13" at 3150,4525 h35
  text "PE12" at 3485,4525 h35
  text "PD6" at 450.1,4425.1 h35
  text "GND" at 785,4425 h35
  text "GND" at 3485,4425 h35
  text "PE11" at 3150,4420 h35
  text "PD7" at 455,4325 h35
  text "PG9" at 785,4325 h35
  text "PD15" at 3150,4325 h35
  text "PD14" at 3485,4325 h35
  text "USB" at 175,4275 h40
  text "PG10" at 455,4225 h35
  text "PG11" at 785,4225 h35
  text "PE9" at 3150,4225 h35
  text "PE10" at 3485,4225 h35
  text "QST" at 3910,4175 h40 r90
  text "PG12" at 455,4125 h35
  text "PG13" at 785,4125 h35
  text "PE7" at 3150,4125 h35
  text "PE8" at 3485,4125 h35
  text "PG14" at 450,4025 h35
  text "PG15" at 785,4025 h35
  text "PG1" at 3150,4025 h35
  text "GND" at 450,3925 h35
  text "PB3" at 785,3925 h35
  text "GND" at 3150,3925 h35
  text "PG0" at 3485,3925 h35
  text "PB4" at 450,3825 h35
  text "PB5" at 785,3825 h35
  text "PF14" at 3150,3825 h35
  text "PF15" at 3485,3825 h35
  text "TRACE" at 3780,3775 h40 r90
  text "1" at 4175,3770 h35 r90
  text "PB6" at 450,3725 h35
  text "PB7" at 785,3725 h35
  text "PF12" at 3150,3725 h35
  text "PF13" at 3485,3725 h35
  text "USART2" at 70,3655 h40
  text "PB8" at 450,3625 h35
  text "PB9" at 785,3625 h35
  text "PB2" at 3165,3625 h35
  text "PF11" at 3485,3625 h35
  text "PE0" at 450,3525 h35
  text "3V3" at 785,3525 h35
  text "Pin1" at 1340,3525 h30
  text "PB1" at 3165,3525 h35
  text "D5V" at 450,3425 h35
  text "GND" at 785,3425 h35
  text "GND" at 3485,3425 h35
  text "1" at 3095,3365 h40 r90
  text "PE4" at 450,3325 h35
  text "PE3" at 785,3325 h35
  text "PB0" at 3165,3325 h35
  text "PC5" at 3490,3325 h35
  text "JTAG" at 3910,3295 h40 r90
  text "VREF" at 2325,3255 h35
  text "PE6" at 450,3225 h35
  text "PE5" at 785,3225 h35
  text "PC4" at 3165,3225 h35
  text "PA7" at 3485,3225 h35
  text "0" at 3095,3165 h40 r90
  text "PC14" at 450,3125 h35
  text "PC13" at 785,3125 h35
  text "PA6" at 3165,3125 h35
  text "PA5" at 3485,3125 h35
  text "Temp" at 1365,3040 h35
  text "PF0" at 450,3025 h35
  text "PC15" at 785,3025 h35
  text "PA4" at 3165,3025 h35
  text "PA3" at 3485,3025 h35
  text "1" at 2475,2985 h40
  text "0" at 2590,2985 h40
  text "BOOT" at 2750,2985 h40
  text "GND" at 450,2925 h35
  text "PF1" at 785,2925 h35
  text "GND" at 3165,2925 h35
  text "PA2" at 3485,2925 h35
  text "X" at 2475,2915 h40
  text "0" at 2590,2915 h40
  text "User  Flash" at 2685,2915 h40
  text "MCU_3V3" at 2075,2900 h35
  text "USB: USB 5V power source" at 1115,2870 h36
  text "0" at 2475,2845 h40
  text "1" at 2595,2845 h40
  text "System memory" at 2685,2845 h40
  text "PF2" at 450,2825 h35
  text "PF3" at 785,2825 h35
  text "PA1" at 3165,2825 h35
  text "DTB: Daughter Board power source" at 1115,2820 h36
  text "1" at 2480,2775 h40
  text "1" at 2595,2775 h40
  text "SRAM" at 2685,2775 h40
  text "PSU: Power Supply Unit" at 1115,2765 h36
  text "5V" at 927.02,2747.98 h35
  text "3V3" at 2325,2735 h35
  text "PF4" at 450,2725 h35
  text "PF5" at 785,2725 h35
  text "PC3" at 3165,2725 h35
  text "PC2" at 3485,2725 h35
  text "LIN" at 2160,2680 h35
  text "PF6" at 450,2625 h35
  text "PF7" at 785,2625 h35
  text "PC1" at 3165,2625 h35
  text "PC0" at 3485,2625 h35
  text "PSU" at 1275,2615 h35 r90
  text "USB" at 1075,2610 h35 r90
  text "DTB" at 1175,2610 h35 r90
  text "MCKO" at 2420,2580 h35 r90
  text "HPR" at 2620,2575 h35 r90
  text "PF8" at 450,2525 h35
  text "PF9" at 785,2525 h35
  text "PF10" at 3165,2520 h35
  text "RIN" at 2160,2510 h35
  text "3V3" at 450,2430 h35
  text "GND" at 785,2425 h35
  text "3V3" at 3165,2425 h35
  text "GND" at 3485,2425 h35
  text "1" at 4175,2420 h35 r90
  text "OFF" at 1710,2400 h35 r90
  text "MCKI" at 1885,2400 h35 r90
  text "CMDVCC" at 1535,2390 h35 r90
  text "HPL" at 2290,2355 h35
  text "MCO" at 2480,2355 h35
  text "USART1" at 75,2350 h40
  text "69" at 600,2345 h35
  text "70" at 700,2345 h35
  text "USB disconnect" at 1355,2345 h35 r90
  text "1" at 1415,2345 h35
  text "69" at 3300,2345 h35
  text "70" at 3400,2345 h35
  text "RST" at 2649.14,2340 h35
  text "MC_PFC" at 2770,2340 h35
  text "Smart Card" at 1530,2335 h40
  text "1" at 1940,2325 h35
  text "S" at -125,1995 h50 r90
  text "D" at -15,1995 h50 r90
  text "MSD" at 3600,1750 h40 r90
  text "Audio JACK" at 3675,1390 h40 r90
  text "IrDA_RX" at 3760,1325 h35
  text "IrDA" at 4250,900 h40 r90
  text "PF9 . . PF6" at 1820,520 h40
  text "-" at 360,505 h40
  text "AUX2" at 685,460 h35
  text "AUX1" at 880,460 h35
  text "+" at 355,325 h40
  text "D" at 3560,320 h45
  text "PSU" at 260,210 h40
  text "ADC12_14" at 3690,170 h35
  text "DC5V" at 260,145 h40
  text "GND" at 230,-125 h35
BottomOverlay:
  drawing of 798 lines, arcs and shapes, not listed
  text "D" at 1365,5300 h45
  text "B" at -125,2650 h50 r90
  text "D" at -15,2650 h50 r90
  text "Smart Card" at 2495,1225 h40
  text "NC" at 2030,1070 h35 r270
  text "CLK" at 2125,1070 h35 r270
  text "RST" at 2225,1070 h35 r270
  text "VCC" at 2325,1070 h35 r270
  text "NC" at 2025,-185 h35 r270
  text "I/O" at 2125,-185 h35 r270
  text "NC" at 2225,-185 h35 r270
  text "GND" at 2325,-185 h35 r270
Mechanical1:
  lines w5: -225,-225 4275,-225 4275,1870 cw(c5430.29,2115.57) 4275,2361.13 4275,6575 -225,6575 -225,-225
